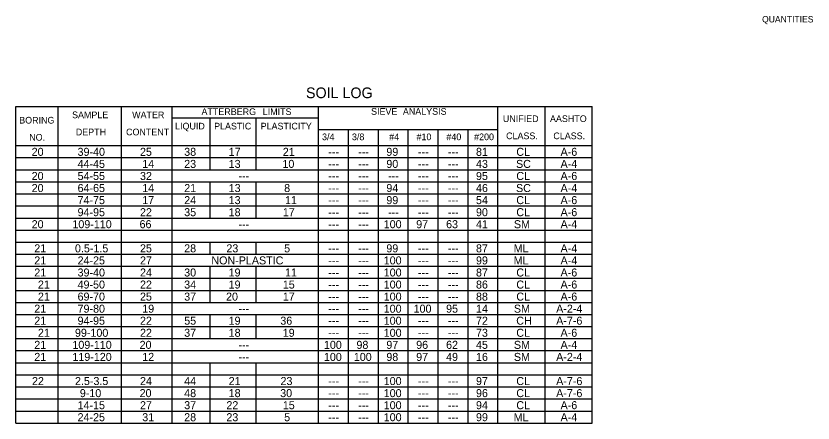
# Model space of a CAD drawing. Extents: x 1197542 to 1207464, y 185022 to 237324.
# Drawn here: x 1207298.3 to 1207447.6, y 185142.6 to 185218.9 of the extents above; entities that cross this region are included whole.
import ezdxf

# ---------------------------------------------------------------- set-up
doc = ezdxf.new("R2010")
doc.units = 0
doc.layers.add('R_Border', color=7, linetype='Continuous')
doc.layers.add('R_No Plot', color=7, linetype='Continuous')

msp = doc.modelspace()

# ---------------------------------------------------------------- linework, layer by layer
at = {"layer": 'R_No Plot'}
for p, q in [((1207298.31, 185201.94), (1207298.31, 185201.94)), ((1207298.31, 185201.94), (1207406.24, 185201.94)), ((1207298.31, 185142.64), (1207298.31, 185201.94)), ((1207306.21, 185142.64), (1207306.21, 185201.94)), ((1207318.05, 185142.64), (1207318.05, 185201.94)), ((1207327.55, 185142.64), (1207327.55, 185201.94)), ((1207354.99, 185142.64), (1207354.99, 185201.94)), ((1207388.57, 185142.64), (1207388.57, 185201.94)), ((1207397.41, 185142.64), (1207397.41, 185201.94)), ((1207406.24, 185142.64), (1207406.24, 185201.94)), ((1207327.55, 185199.78), (1207354.99, 185199.78)), ((1207334.71, 185190.08), (1207334.71, 185199.78)), ((1207343.29, 185190.08), (1207343.29, 185199.78)), ((1207354.99, 185197.62), (1207388.57, 185197.62)), ((1207360.58, 185142.64), (1207360.58, 185197.62)), ((1207366.18, 185142.64), (1207366.18, 185197.62)), ((1207371.78, 185142.64), (1207371.78, 185197.62)), ((1207377.38, 185142.64), (1207377.38, 185197.62)), ((1207382.98, 185142.64), (1207382.98, 185197.62)), ((1207298.31, 185194.6), (1207406.24, 185194.6)), ((1207388.57, 185194.6), (1207406.24, 185194.6)), ((1207298.31, 185192.34), (1207406.24, 185192.34)), ((1207298.31, 185190.08), (1207406.24, 185190.08)), ((1207298.31, 185187.82), (1207406.24, 185187.82)), ((1207334.71, 185181.04), (1207334.71, 185187.82)), ((1207343.29, 185181.04), (1207343.29, 185187.82)), ((1207298.31, 185185.56), (1207406.24, 185185.56)), ((1207298.31, 185183.3), (1207406.24, 185183.3)), ((1207298.31, 185181.04), (1207406.24, 185181.04)), ((1207298.31, 185178.78), (1207406.24, 185178.78)), ((1207298.31, 185176.53), (1207406.24, 185176.53)), ((1207334.71, 185174.27), (1207334.71, 185176.53)), ((1207343.29, 185174.27), (1207343.29, 185176.53)), ((1207298.31, 185174.27), (1207406.24, 185174.27)), ((1207298.31, 185172.01), (1207406.24, 185172.01)), ((1207334.71, 185165.23), (1207334.71, 185172.01)), ((1207343.29, 185165.23), (1207343.29, 185172.01)), ((1207298.31, 185169.75), (1207406.24, 185169.75)), ((1207298.31, 185167.49), (1207406.24, 185167.49)), ((1207298.31, 185165.23), (1207406.24, 185165.23)), ((1207298.31, 185162.97), (1207406.24, 185162.97)), ((1207334.71, 185158.46), (1207334.71, 185162.97)), ((1207343.29, 185158.46), (1207343.29, 185162.97)), ((1207298.31, 185160.71), (1207406.24, 185160.71)), ((1207298.31, 185158.46), (1207406.24, 185158.46)), ((1207298.31, 185156.2), (1207406.24, 185156.2)), ((1207298.31, 185153.94), (1207406.24, 185153.94)), ((1207334.71, 185142.64), (1207334.71, 185153.94)), ((1207343.29, 185142.64), (1207343.29, 185153.94)), ((1207298.31, 185151.68), (1207406.24, 185151.68)), ((1207298.31, 185149.42), (1207406.24, 185149.42)), ((1207298.31, 185147.16), (1207406.24, 185147.16)), ((1207298.31, 185144.9), (1207406.24, 185144.9)), ((1207298.31, 185142.64), (1207406.24, 185142.64))]:
    msp.add_line(p, q, dxfattribs=at)

# ---------------------------------------------------------------- texts
at = {"layer": 'R_Border'}
msp.add_text('QUANTITIES', height=1.2, rotation=360, dxfattribs=at).set_placement((1207438.05, 185217.66))
at = {"layer": 'R_No Plot'}
for s, height, p in [('SOIL LOG', 2, (1207352.63, 185203.48)), ('SAMPLE', 1.25, (1207308.82, 185199.73)), ('WATER', 1.25, (1207320.07, 185199.73)), ('ATTERBERG', 1.25, (1207333.06, 185200.32)), ('LIMITS', 1.25, (1207344.53, 185200.32)), ('SIEVE', 1.25, (1207364.82, 185200.37)), ('ANALYSIS', 1.25, (1207370.78, 185200.37)), ('UNIFIED', 1.25, (1207389.51, 185199.01)), ('AASHTO', 1.25, (1207398.33, 185199.01)), ('BORING', 1.25, (1207298.92, 185198.73)), ('LIQUID', 1.25, (1207328.11, 185197.62)), ('PLASTIC', 1.25, (1207335.42, 185197.62)), ('PLASTICITY', 1.25, (1207344.14, 185197.62)), ('DEPTH', 1.25, (1207309.52, 185196.52)), ('CONTENT', 1.25, (1207318.93, 185196.52)), ('NO.', 1.25, (1207300.79, 185195.53)), ('3/4', 1.25, (1207355.64, 185195.61)), ('3/8', 1.25, (1207361.24, 185195.61)), ('#4', 1.25, (1207368.21, 185195.61)), ('#10', 1.25, (1207373.33, 185195.61)), ('#40', 1.25, (1207378.93, 185195.61)), ('#200', 1.25, (1207384.12, 185195.61)), ('CLASS.', 1.25, (1207390.11, 185195.8)), ('CLASS.', 1.25, (1207398.96, 185195.8)), ('20', 1.5, (1207301.25, 185192.68)), ('39-40', 1.5, (1207309.85, 185192.68)), ('25', 1.5, (1207321.54, 185192.68)), ('38', 1.5, (1207329.82, 185192.68)), ('21', 1.5, (1207348.29, 185192.68)), ('99', 1.5, (1207367.68, 185192.68)), ('81', 1.5, (1207384.47, 185192.68)), ('CL', 1.5, (1207392.02, 185192.68)), ('A-6', 1.5, (1207400.31, 185192.68)), ('17', 1.5, (1207338.15, 185192.68)), ('---', 1.5, (1207356.81, 185192.68)), ('---', 1.5, (1207362.41, 185192.68)), ('---', 1.5, (1207373.61, 185192.68)), ('---', 1.5, (1207379.21, 185192.68)), ('44-45', 1.5, (1207309.85, 185190.42)), ('14', 1.5, (1207321.96, 185190.42)), ('23', 1.5, (1207329.82, 185190.42)), ('13', 1.5, (1207338.15, 185190.42)), ('10', 1.5, (1207348.22, 185190.42)), ('90', 1.5, (1207367.68, 185190.42)), ('43', 1.5, (1207384.47, 185190.42)), ('SC', 1.5, (1207391.97, 185190.42)), ('A-4', 1.5, (1207400.31, 185190.42)), ('---', 1.5, (1207356.81, 185190.42)), ('---', 1.5, (1207362.41, 185190.42)), ('---', 1.5, (1207373.61, 185190.42)), ('---', 1.5, (1207379.21, 185190.42)), ('20', 1.5, (1207301.25, 185188.16)), ('54-55', 1.5, (1207309.85, 185188.16)), ('32', 1.5, (1207321.54, 185188.16)), ('---', 1.5, (1207339.99, 185188.16)), ('---', 1.5, (1207356.81, 185188.16)), ('---', 1.5, (1207362.41, 185188.16)), ('---', 1.5, (1207368.01, 185188.16)), ('---', 1.5, (1207373.61, 185188.16)), ('---', 1.5, (1207379.21, 185188.16)), ('95', 1.5, (1207384.47, 185188.16)), ('CL', 1.5, (1207392.02, 185188.16)), ('A-6', 1.5, (1207400.31, 185188.16)), ('20', 1.5, (1207301.25, 185185.9)), ('64-65', 1.5, (1207309.85, 185185.9)), ('14', 1.5, (1207321.96, 185185.9)), ('21', 1.5, (1207329.82, 185185.9)), ('13', 1.5, (1207338.15, 185185.9)), ('8', 1.5, (1207348.54, 185185.9)), ('94', 1.5, (1207367.68, 185185.9)), ('46', 1.5, (1207384.47, 185185.9)), ('SC', 1.5, (1207391.97, 185185.9)), ('A-4', 1.5, (1207400.31, 185185.9)), ('---', 1.5, (1207356.81, 185185.9)), ('---', 1.5, (1207362.41, 185185.9)), ('---', 1.5, (1207373.61, 185185.9)), ('---', 1.5, (1207379.21, 185185.9)), ('74-75', 1.5, (1207309.85, 185183.64)), ('17', 1.5, (1207321.96, 185183.64)), ('24', 1.5, (1207329.82, 185183.64)), ('13', 1.5, (1207338.15, 185183.64)), ('11', 1.5, (1207348.71, 185183.64)), ('---', 1.5, (1207356.81, 185183.64)), ('---', 1.5, (1207362.41, 185183.64)), ('99', 1.5, (1207367.68, 185183.64)), ('---', 1.5, (1207373.61, 185183.64)), ('---', 1.5, (1207379.21, 185183.64)), ('54', 1.5, (1207384.47, 185183.64)), ('CL', 1.5, (1207392.02, 185183.64)), ('A-6', 1.5, (1207400.31, 185183.64)), ('94-95', 1.5, (1207309.85, 185181.38)), ('22', 1.5, (1207321.54, 185181.38)), ('35', 1.5, (1207329.82, 185181.38)), ('18', 1.5, (1207338.15, 185181.38)), ('17', 1.5, (1207348.29, 185181.38)), ('90', 1.5, (1207384.47, 185181.38)), ('CL', 1.5, (1207392.02, 185181.38)), ('A-6', 1.5, (1207400.31, 185181.38)), ('---', 1.5, (1207356.81, 185181.38)), ('---', 1.5, (1207362.41, 185181.38)), ('---', 1.5, (1207368.01, 185181.38)), ('---', 1.5, (1207373.61, 185181.38)), ('---', 1.5, (1207379.21, 185181.38)), ('20', 1.5, (1207301.25, 185179.13)), ('109-110', 1.5, (1207308.88, 185179.13)), ('66', 1.5, (1207321.46, 185179.13)), ('---', 1.5, (1207339.99, 185179.13)), ('---', 1.5, (1207356.81, 185179.13)), ('---', 1.5, (1207362.41, 185179.13)), ('100', 1.5, (1207367.19, 185179.13)), ('97', 1.5, (1207373.27, 185179.13)), ('63', 1.5, (1207378.87, 185179.13)), ('41', 1.5, (1207384.47, 185179.13)), ('SM', 1.5, (1207391.57, 185179.13)), ('A-4', 1.5, (1207400.31, 185179.13)), ('21', 1.5, (1207301.74, 185174.61)), ('0.5-1.5', 1.5, (1207309.36, 185174.61)), ('25', 1.5, (1207321.54, 185174.61)), ('28', 1.5, (1207329.82, 185174.61)), ('23', 1.5, (1207337.72, 185174.61)), ('5', 1.5, (1207348.54, 185174.61)), ('---', 1.5, (1207356.81, 185174.61)), ('---', 1.5, (1207362.41, 185174.61)), ('99', 1.5, (1207367.68, 185174.61)), ('---', 1.5, (1207373.61, 185174.61)), ('---', 1.5, (1207379.21, 185174.61)), ('87', 1.5, (1207384.47, 185174.61)), ('ML', 1.5, (1207391.53, 185174.61)), ('A-4', 1.5, (1207400.31, 185174.61)), ('21', 1.5, (1207301.74, 185172.35)), ('24-25', 1.5, (1207309.85, 185172.35)), ('27', 1.5, (1207321.54, 185172.35)), ('NON-PLASTIC', 1.5, (1207334.91, 185172.35)), ('100', 1.5, (1207367.19, 185172.35)), ('99', 1.5, (1207384.47, 185172.35)), ('ML', 1.5, (1207391.53, 185172.35)), ('A-4', 1.5, (1207400.31, 185172.35)), ('---', 1.5, (1207356.81, 185172.35)), ('---', 1.5, (1207362.41, 185172.35)), ('---', 1.5, (1207373.61, 185172.35)), ('---', 1.5, (1207379.21, 185172.35)), ('21', 1.5, (1207301.74, 185170.09)), ('39-40', 1.5, (1207309.85, 185170.09)), ('24', 1.5, (1207321.54, 185170.09)), ('30', 1.5, (1207329.82, 185170.09)), ('19', 1.5, (1207338.14, 185170.09)), ('11', 1.5, (1207348.71, 185170.09)), ('---', 1.5, (1207356.81, 185170.09)), ('---', 1.5, (1207362.41, 185170.09)), ('100', 1.5, (1207367.19, 185170.09)), ('---', 1.5, (1207373.61, 185170.09)), ('---', 1.5, (1207379.21, 185170.09)), ('87', 1.5, (1207384.47, 185170.09)), ('CL', 1.5, (1207392.02, 185170.09)), ('A-6', 1.5, (1207400.31, 185170.09)), ('21', 1.5, (1207302.42, 185167.83)), ('49-50', 1.5, (1207309.85, 185167.83)), ('22', 1.5, (1207321.54, 185167.83)), ('34', 1.5, (1207329.82, 185167.83)), ('19', 1.5, (1207338.14, 185167.83)), ('15', 1.5, (1207348.29, 185167.83)), ('100', 1.5, (1207367.19, 185167.83)), ('86', 1.5, (1207384.47, 185167.83)), ('CL', 1.5, (1207392.02, 185167.83)), ('A-6', 1.5, (1207400.31, 185167.83)), ('---', 1.5, (1207356.81, 185167.83)), ('---', 1.5, (1207362.41, 185167.83)), ('---', 1.5, (1207373.61, 185167.83)), ('---', 1.5, (1207379.21, 185167.83)), ('21', 1.5, (1207302.42, 185165.57)), ('69-70', 1.5, (1207309.85, 185165.57)), ('25', 1.5, (1207321.54, 185165.57)), ('37', 1.5, (1207329.82, 185165.57)), ('20', 1.5, (1207337.66, 185165.57)), ('17', 1.5, (1207348.29, 185165.57)), ('---', 1.5, (1207356.81, 185165.57)), ('---', 1.5, (1207362.41, 185165.57)), ('100', 1.5, (1207367.19, 185165.57)), ('---', 1.5, (1207373.61, 185165.57)), ('---', 1.5, (1207379.21, 185165.57)), ('88', 1.5, (1207384.47, 185165.57)), ('CL', 1.5, (1207392.02, 185165.57)), ('A-6', 1.5, (1207400.31, 185165.57)), ('21', 1.5, (1207301.74, 185163.31)), ('79-80', 1.5, (1207309.85, 185163.31)), ('19', 1.5, (1207321.96, 185163.31)), ('100', 1.5, (1207367.19, 185163.31)), ('100', 1.5, (1207372.79, 185163.31)), ('95', 1.5, (1207378.87, 185163.31)), ('14', 1.5, (1207384.47, 185163.31)), ('SM', 1.5, (1207391.57, 185163.31)), ('A-2-4', 1.5, (1207399.49, 185163.31)), ('---', 1.5, (1207339.99, 185163.32)), ('---', 1.5, (1207356.81, 185163.31)), ('---', 1.5, (1207362.41, 185163.31)), ('21', 1.5, (1207301.74, 185161.06)), ('94-95', 1.5, (1207309.85, 185161.06)), ('22', 1.5, (1207321.54, 185161.06)), ('55', 1.5, (1207329.82, 185161.06)), ('19', 1.5, (1207338.14, 185161.06)), ('36', 1.5, (1207347.82, 185161.06)), ('---', 1.5, (1207356.81, 185161.06)), ('---', 1.5, (1207362.41, 185161.06)), ('100', 1.5, (1207367.19, 185161.06)), ('---', 1.5, (1207373.61, 185161.06)), ('---', 1.5, (1207379.21, 185161.06)), ('72', 1.5, (1207384.47, 185161.06)), ('CH', 1.5, (1207392.01, 185161.06)), ('A-7-6', 1.5, (1207399.49, 185161.06)), ('21', 1.5, (1207302.42, 185158.8)), ('99-100', 1.5, (1207309.36, 185158.8)), ('22', 1.5, (1207321.54, 185158.8)), ('37', 1.5, (1207329.82, 185158.8)), ('18', 1.5, (1207338.15, 185158.8)), ('19', 1.5, (1207348.28, 185158.8)), ('100', 1.5, (1207367.19, 185158.8)), ('73', 1.5, (1207384.47, 185158.8)), ('CL', 1.5, (1207392.02, 185158.8)), ('A-6', 1.5, (1207400.31, 185158.8)), ('---', 1.5, (1207356.81, 185158.8)), ('---', 1.5, (1207362.41, 185158.8)), ('---', 1.5, (1207373.61, 185158.8)), ('---', 1.5, (1207379.21, 185158.8)), ('21', 1.5, (1207301.74, 185156.54)), ('109-110', 1.5, (1207308.88, 185156.54)), ('20', 1.5, (1207321.47, 185156.54)), ('---', 1.5, (1207339.99, 185156.54)), ('100', 1.5, (1207355.99, 185156.54)), ('98', 1.5, (1207362.08, 185156.54)), ('97', 1.5, (1207367.68, 185156.54)), ('96', 1.5, (1207373.27, 185156.54)), ('62', 1.5, (1207378.87, 185156.54)), ('45', 1.5, (1207384.47, 185156.54)), ('SM', 1.5, (1207391.57, 185156.54)), ('A-4', 1.5, (1207400.31, 185156.54)), ('21', 1.5, (1207301.74, 185154.28)), ('119-120', 1.5, (1207308.88, 185154.28)), ('12', 1.5, (1207321.96, 185154.28)), ('100', 1.5, (1207355.99, 185154.28)), ('100', 1.5, (1207361.59, 185154.28)), ('98', 1.5, (1207367.68, 185154.28)), ('97', 1.5, (1207373.27, 185154.28)), ('49', 1.5, (1207378.87, 185154.28)), ('16', 1.5, (1207384.47, 185154.28)), ('SM', 1.5, (1207391.57, 185154.28)), ('A-2-4', 1.5, (1207399.49, 185154.28)), ('---', 1.5, (1207339.99, 185154.28)), ('22', 1.5, (1207301.31, 185149.76)), ('2.5-3.5', 1.5, (1207309.36, 185149.76)), ('24', 1.5, (1207321.54, 185149.76)), ('44', 1.5, (1207329.82, 185149.76)), ('21', 1.5, (1207338.15, 185149.76)), ('23', 1.5, (1207347.86, 185149.76)), ('100', 1.5, (1207367.19, 185149.76)), ('97', 1.5, (1207384.47, 185149.76)), ('CL', 1.5, (1207392.02, 185149.76)), ('A-7-6', 1.5, (1207399.49, 185149.76)), ('---', 1.5, (1207356.81, 185149.76)), ('---', 1.5, (1207362.41, 185149.76)), ('---', 1.5, (1207373.61, 185149.76)), ('---', 1.5, (1207379.21, 185149.76)), ('9-10', 1.5, (1207310.27, 185147.5)), ('20', 1.5, (1207321.47, 185147.5)), ('48', 1.5, (1207329.82, 185147.5)), ('18', 1.5, (1207338.15, 185147.5)), ('30', 1.5, (1207347.8, 185147.5)), ('---', 1.5, (1207356.81, 185147.5)), ('---', 1.5, (1207362.41, 185147.5)), ('100', 1.5, (1207367.19, 185147.5)), ('---', 1.5, (1207373.61, 185147.5)), ('---', 1.5, (1207379.21, 185147.5)), ('96', 1.5, (1207384.47, 185147.5)), ('CL', 1.5, (1207392.02, 185147.5)), ('A-7-6', 1.5, (1207399.49, 185147.5)), ('14-15', 1.5, (1207309.85, 185145.24)), ('27', 1.5, (1207321.54, 185145.24)), ('37', 1.5, (1207329.82, 185145.24)), ('22', 1.5, (1207337.72, 185145.24)), ('15', 1.5, (1207348.29, 185145.24)), ('100', 1.5, (1207367.19, 185145.24)), ('94', 1.5, (1207384.47, 185145.24)), ('CL', 1.5, (1207392.02, 185145.24)), ('A-6', 1.5, (1207400.31, 185145.24)), ('---', 1.5, (1207356.81, 185145.24)), ('---', 1.5, (1207362.41, 185145.24)), ('---', 1.5, (1207373.61, 185145.24)), ('---', 1.5, (1207379.21, 185145.24)), ('24-25', 1.5, (1207309.85, 185142.99)), ('31', 1.5, (1207321.96, 185142.99)), ('28', 1.5, (1207329.82, 185142.99)), ('23', 1.5, (1207337.72, 185142.99)), ('5', 1.5, (1207348.54, 185142.99)), ('---', 1.5, (1207356.81, 185142.99)), ('---', 1.5, (1207362.41, 185142.99)), ('100', 1.5, (1207367.19, 185142.99)), ('---', 1.5, (1207373.61, 185142.99)), ('---', 1.5, (1207379.21, 185142.99)), ('99', 1.5, (1207384.47, 185142.99)), ('ML', 1.5, (1207391.53, 185142.99)), ('A-4', 1.5, (1207400.31, 185142.99))]:
    msp.add_text(s, height=height, dxfattribs=at).set_placement(p)

doc.saveas('drawing.dxf')
